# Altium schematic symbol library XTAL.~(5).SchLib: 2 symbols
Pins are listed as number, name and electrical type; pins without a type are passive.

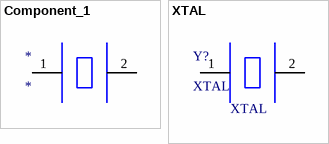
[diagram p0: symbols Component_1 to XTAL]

## Component_1
designator *
pins: 1, 2

## XTAL
designator Y?
footprint XTAL
pins: 1, 2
